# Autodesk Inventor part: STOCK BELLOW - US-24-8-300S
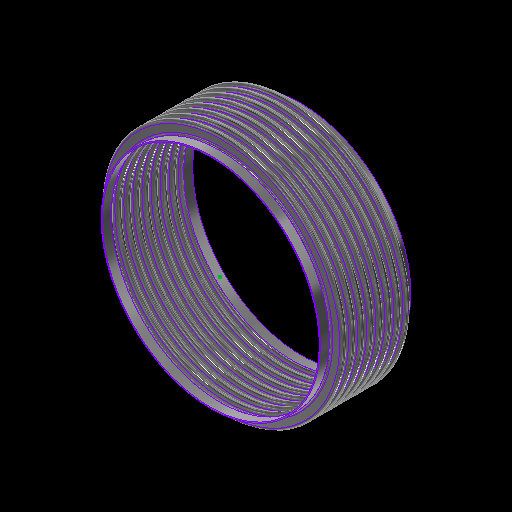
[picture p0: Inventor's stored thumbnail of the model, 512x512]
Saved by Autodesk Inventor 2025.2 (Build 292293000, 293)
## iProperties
Category: 16 GA (0.060 THICK)
RuleStatus: InUse
Created: 2024-01
Part Number: STOCK BELLOW - US-24-8-300S
Project: =STOCK BELLOWS: <Stock Number><SFILL>
Material: ASTM A240-304
Description: =STOCK BELLOWS: <Stock Number>, <SID_> I.D., <SOD_> O.D., <SPLY_> PLY, <Category>, <SNET_CONS> CONS.<PITCH_><STANGENT_> TANGENT<SFILL>
Document SubType Name: Sheet Metal
Designer: GS
Stock Number: U.S-24-8-300S
Surface Area: 27659.1 cm^2
Volume: 4161.61 cm^3
Sheet Metal Rule: Default
Appearance: STAINLESS STEEL
Mass: 33531.3 g
Density: 8.05729 g/cm^3
THK: 0.036
ID: 3.500
OD: 4.250
CONS_: 2
PITCH: 0.500
TANGENT: 0.500
BELLOWS_UPSET: 0.000
d79: 1.000
d82: 1.000
d83: 26.000
d84: 24.000
d174: 8
d214: 8
STHK_: 0.060
SID_: 24.000
SOD_: 26.750
SPITCH_: 1.000
STANGENT__: 1.000
SBELLOWS_UPSET_: 0.000
SDIFF_TAN: 1.000
d252: 2
d275: 2
d287: 0.050
d289: 0.500
d290: 0.000
SOD_NECK: 24 1/4
PLY: 1
PSET: 4.178
PBAR: 1.035
COUNTER: 1.500
NET_TUBE: 3.071
CONS: 2
S_CONS: 0
NET_CONS: 2
ID_M: 88.90 mm
OD_M: 107.95 mm
THK_M: 0.91 mm
ID_U: 3.500 in
OD_U: 4.250 in
THK_U: 0.036 in
TANGENT2: 0.500
TAN_TO_TAN: 1.000 in
d80: 2.571
d81: 10
SID: 2.375
SCONS_: 8
SPITCH: 0.250
STANGENT_: 1.000
SBELLOWS_UPSET: 0.000
SNET_CONS: 8
SS_CONS: 0
SCONS: 8
d190: 8
d191: 1
d192: 1
d193: 8
d194: 0
SIZE: 24.00
PRESSURE: 300
d230: 8
STANGENT: 4.000
SPLY_: 2
d233: 8
d234: 0
d263: 2
d265: 1
d268: 2
d269: 0
d286: 2
d288: 1
d291: 2
d292: 0
SREROLL: 0.750
BLETP: 0.000 ul
PRES_Copy: 85
MATTABLE: 20 GA (0.036 THICK)
PART_NUMBER: U.S-24-8-300S
PITCH_: =, <SPITCH_> PITCH,
CFILL: .
SFILL: .
MESH: ,
COMP: 1.6
EXT: 0.80
LAT: 0.15
ANG: 392
ASR: 10396
LSR: 156893
ANSR: 14604
PRES: 300
COMPM: 16.0
EXTM: 8.0
LATM: 1.50
ASRM: 1820.651
PRESM: 20.684
LSRM: 27476.671
ANSRM: 2557.599
TEMPMIN: 20
TEMPMAX: 800
TEMPMINM: -7
TEMPMAXM: 427
WEIGHTM: 33.531
WEIGHT: 73.924
Author: GS
Keywords: 20 GA (0.036 THICK)
Comments: =STOCK BELLOW - <STOCK NUMBER>
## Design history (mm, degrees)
sketch "Sketch2"
  geometry: L1 (0, -177.245)-(0, 562.856) reference; L2 (45.364, 0)-(44.45, 0); L3 (48.082, -2.718)-(50.343, -2.718); L4 (48.082, -3.632)-(50.343, -3.632); L5 (50.343, -9.982)-(48.082, -9.982); L6 (50.343, -9.068)-(48.082, -9.068); L7 (45.364, -12.7)-(44.45, -12.7); L8 (48.082, 0)-(48.082, -12.7); L9 (50.343, -6.35)-(53.975, -6.35); L10 (44.45, 0)-(44.45, -12.7); L11 (20.376, 102.841)-(20.376, 101.926); L12 (58.262, 457.127)-(58.262, 349.177); L13 (58.262, 444.427)-(58.262, 336.477); L14 (93.133, -58.817)-(93.133, -71.517); L15 (118.746, -66.401)-(118.746, -66.401); L16 (50.343, -9.068)-(50.343, -9.982); L17 (48.082, -9.068)-(48.082, -9.982); L18 (48.082, -9.525)-(50.343, -9.525); L19 (53.975, 0)-(53.975, -12.7); L20 (-50.343, -9.068)-(-50.343, -9.982); L21 (-50.343, -2.718)-(-48.082, -2.718); L22 (-50.343, -3.632)-(-48.082, -3.632); L23 (-48.082, -9.068)-(-50.343, -9.068); L24 (-50.343, -9.525)-(-48.082, -9.525); L25 (-48.082, -9.982)-(-50.343, -9.982); L26 (-48.082, -9.068)-(-48.082, -9.982); L27 (-44.45, 0.653)-(-44.45, -12.047); L28 (-48.082, -6.35)-(-44.45, -6.35); L29 (-50.343, 0.653)-(-50.343, -12.7); L30 (-53.061, 0)-(-53.975, 0); L31 (-53.975, 0)-(-53.975, -12.7); L32 (-53.061, -12.7)-(-53.975, -12.7); A1 r 2.718 centre (48.082, 0) between (45.364, 0) and (48.082, -2.718); A2 r 3.632 centre (48.082, 0) between (44.45, 0) and (48.082, -3.632); A3 r 3.632 centre (50.343, -6.35) between (50.343, -9.982) and (50.343, -2.718); A4 r 2.718 centre (50.343, -6.35) between (50.343, -9.068) and (50.343, -3.632); A5 r 2.718 centre (48.082, -12.7) between (48.082, -9.982) and (45.364, -12.7); A6 r 3.632 centre (48.082, -12.7) between (48.082, -9.068) and (44.45, -12.7); A7 r 3.175 centre (50.343, -6.35) between (50.343, -9.525) and (53.518, -6.35); A8 r 3.175 centre (48.082, -12.7) between (48.082, -9.525) and (44.907, -12.7); A9 r 2.718 centre (-50.343, -12.7) between (-50.343, -9.982) and (-53.061, -12.7); A10 r 2.718 centre (-48.082, -6.35) between (-48.082, -9.068) and (-48.082, -3.632); A11 r 3.175 centre (-48.082, -6.35) between (-48.082, -9.525) and (-44.907, -6.35); A12 r 3.632 centre (-48.082, -6.35) between (-48.082, -9.982) and (-48.082, -2.718); A13 r 3.175 centre (-50.343, -12.7) between (-50.343, -9.525) and (-53.518, -12.7); A14 r 3.632 centre (-50.343, -12.7) between (-50.343, -9.068) and (-53.975, -12.7); A15 r 2.718 centre (-50.343, 0) between (-53.061, 0) and (-50.343, -2.718); A16 r 3.632 centre (-50.343, 0) between (-53.975, 0) and (-50.343, -3.632); 10 further points
  constraints: 62 end point, 38 point on circle, 20 tangent, 16 centre point, 12 parallel, 9 midpoint, 7 vertical, 6 coincident, 6 concentric, 6 point on line, 4 equal radius, 4 perpendicular, 3 horizontal, 1 collinear, 1 horizontal alignment, 10 other
  dimensions: "THK" = 0.9144 distance of L11.start L11.end; "ID" = 88.9 distance of L11.end point (20.376, 13.026); "OD" = 107.95 distance of L12.start L12.end; "PITCH" = 12.7 distance of L12.start L13.start; "TANGENT" = 12.7 distance of L14.start L14.end; "BELLOWS_UPSET" = 0 distance of L15.start L15.end; "d43" = 88.9 diameter of L10 L1 (= ID); "d44" = 107.95 diameter of L9.end L1 (= OD); "d45" = 0.9144 distance between parallel lines of L5 L6 (computed from THK, PLY); "d46" = 3.6322 radius of A3 (computed from PITCH, THK, PLY); "UPSET_PITCH" = 12.7 distance of L2.end L7.end (derived); "SIDEWALL_ANGLE" = 360 deg dimension on L3 L9 (derived); "CON_GAP" = 5.4356 distance of point (48.082, -9.068) point (48.082, -3.632) (derived); "TAN1" = 4.98728 dimension on A8 (derived); "TAN2" = 4.98728 dimension on A7 (derived); "LEG1" = 2.2606 distance of L18.start L18.end (derived); "d278" = 0.9144 distance between parallel lines of L25 L23 (derived); "d279" = 3.6322 radius of A12 (derived); "d280" = 12.7 distance of L30.end L31.end (derived); "d281" = 360 deg dimension on L21 L28 (derived); "d282" = 5.4356 distance of point (-50.343, -9.068) point (-50.343, -3.632) (derived); "d283" = 4.98728 dimension on A13 (derived); "d284" = 4.98728 dimension on A11 (derived); "d285" = 2.2606 distance of L24.start L24.end (derived); "d293" = 88.9 diameter of L27 L1 (derived); "d294" = 107.95 diameter of L31 L1 (derived)
  node "Sketch Rectangular Pattern1" dims "d31" = 25.4, "ID" = 88.9
  node "Sketch Rectangular Pattern2" dims "d39" = 25.4, "PITCH" = 12.7
revolve "CONS" stored, may be unused: angle "d48" = 90 deg
node "BELLOW MIDPLANE"
pattern_linear "Rectangular Pattern2" dims "d52" = 12.7 (= UPSET_PITCH)
sketch "Sketch5"
  geometry: C1 r 45.364 at (0, 0) reference; C2 r 44.45 at (0, 0) reference
extrude "TANGENT" new body sketch "Sketch5" distance "d53" = 12.7 (= TANGENT); taper "d54" = 0 deg
revolve "SAMETAN" stored, may be unused: angle "d65" = 90 deg
revolve "DIFFTAN" stored, may be unused: angle "d70" = 90 deg
sketch "Sketch9"
  geometry: L1 (53.319, 0)-(-53.319, 0) reference; L2 (0, -17.78)-(0, 17.78) reference; L3 (38.085, 0)-(-38.085, 0); L4 (38.085, -11.906)-(38.085, 11.906); L5 (25.385, -11.906)-(25.385, 11.906); L6 (13.15, 11.906)-(13.15, -11.906); L7 (-25.385, -11.906)-(-25.385, 11.906); L8 (-38.085, -11.906)-(-38.085, 11.906); L9 (37.291, -11.906)-(37.291, 11.906); L10 (38.085, -11.906)-(37.291, -11.906); L11 (38.085, 11.906)-(37.291, 11.906); L12 (13.546, 11.906)-(12.753, 11.906); L13 (12.753, 11.906)-(12.753, -11.906); L14 (12.753, -11.906)-(13.546, -11.906); L15 (13.546, -11.906)-(13.546, 11.906); L16 (-13.546, 11.906)-(-13.546, -11.906); L17 (-13.15, 11.906)-(-13.15, -11.906); L18 (-13.546, -11.906)-(-12.753, -11.906); L19 (-12.753, -11.906)-(-12.753, 11.906); L20 (-12.753, 11.906)-(-13.546, 11.906); L21 (-38.085, -11.906)-(-37.291, -11.906); L22 (-37.291, -11.906)-(-37.291, 11.906); L23 (-37.291, 11.906)-(-38.085, 11.906); L24 (-38.085, 11.906)-(-38.085, -11.906); L25 (38.085, -0.397)-(-38.085, -0.397); L26 (-38.085, -0.397)-(-38.085, 0.397); L27 (-38.085, 0.397)-(38.085, 0.397); L28 (38.085, 0.397)-(38.085, -0.397); L29 (-38.085, 11.906)-(38.085, 11.906); L30 (38.085, 11.906)-(38.085, 12.7); L31 (38.085, 12.7)-(-38.085, 12.7); L32 (-38.085, 12.7)-(-38.085, 11.906); L33 (38.085, -11.906)-(-38.085, -11.906); L34 (-38.085, -11.906)-(-38.085, -12.7); L35 (-38.085, -12.7)-(38.085, -12.7); L36 (38.085, -12.7)-(38.085, -11.906); 30 further points
  constraints: 68 end point, 13 midpoint, 13 parallel, 8 horizontal, 7 perpendicular, 6 equal length, 3 point on line, 2 vertical, 14 other
  dimensions: "d115" = 23.8125 distance of L4.start L4.end (derived); "d116" = 12.7 distance between parallel lines of L4 L5 (derived); "d117" = 12.23516 distance between parallel lines of L5 L6 (derived); "d125" = 38.53427 distance between parallel lines of L7 L6 (derived); "d127" = 12.7 distance between parallel lines of L8 L7 (derived); "d128" = 24.93516 distance between parallel lines of L6 L4 (derived); "d130" = 76.16943 distance between parallel lines of L8 L4 (derived); "RULER_THK" = 0.79375 distance between parallel lines of L4 L9; "d135" = 0.79375 distance of L13.end L14.end (derived); "d138" = 26.29911 distance of L13.end L16.end (derived); "d143" = 0.79375 distance of L22.end L8.end (derived); "d144" = 0.79375 distance between parallel lines of L27 L25 (derived)
extrude "RULER" join sketch "Sketch9" distance "d149" = 0.79375 (derived); taper "d150" = 0 deg
extrude "BARS" join sketch "Sketch9" distance "d151" = 0.79375 (derived); taper "d152" = 0 deg
pattern_linear "Rectangular Pattern4" dims "d155" = 26.29911 (derived)
sketch "Sketch13"
  geometry: L1 (93.149, -52.467)-(93.149, -77.867); L2 (307.848, 0)-(304.8, 0); L3 (307.848, -25.4)-(304.8, -25.4); L4 (331.851, -20.574)-(312.674, -20.574); L5 (331.851, -17.526)-(312.674, -17.526); L6 (331.851, -12.7)-(339.725, -12.7); L7 (312.674, -4.826)-(331.851, -4.826); L8 (312.674, 0)-(312.674, -25.4); L9 (304.8, 0)-(304.8, -25.4); L10 (58.254, 183.019)-(58.254, -496.431); L11 (58.254, 157.619)-(58.254, -521.831); L12 (58.254, 106.819)-(58.254, -572.631); L13 (58.254, 81.419)-(58.254, -598.031); L14 (58.254, 56.019)-(58.254, -623.431); L15 (58.254, 30.619)-(58.254, -648.831); L16 (58.254, 5.219)-(58.254, -674.231); L17 (58.254, 132.219)-(58.254, -547.231); L18 (20.376, 103.45)-(20.376, 101.926); L19 (312.674, -7.874)-(331.851, -7.874); L20 (0, -845.681)-(0, 354.469) reference; L21 (-67.945, 0)-(407.67, 0) reference; A1 r 4.826 centre (312.674, 0) between (307.848, 0) and (312.674, -4.826); A2 r 4.826 centre (312.674, -25.4) between (312.674, -20.574) and (307.848, -25.4); A3 r 7.874 centre (312.674, -25.4) between (312.674, -17.526) and (304.8, -25.4); A4 r 4.826 centre (331.851, -12.7) between (331.851, -17.526) and (331.851, -7.874); A5 r 7.874 centre (331.851, -12.7) between (331.851, -20.574) and (331.851, -4.826); A6 r 7.874 centre (312.674, 0) between (304.8, 0) and (312.674, -7.874); 6 further points; 1 other entity
  constraints: 38 end point, 15 point on circle, 9 tangent, 6 centre point, 6 parallel, 5 vertical alignment, 4 point on line, 4 vertical, 3 coincident, 3 concentric, 2 collinear, 2 equal radius, 1 horizontal, 1 perpendicular, 23 other
  dimensions: "SBELLOWS_UPSET_" = 0 distance of point (118.762, -66.401) point (118.762, -66.401); "STOTAL_THK_BELLOW__" = 3.048 distance between parallel lines of L4 L5 (derived); "d224" = 7.874 radius of A5 (derived); "d225" = 25.4 distance of L2.end L3.end (derived); "SSIDEWALL_ANGLE_" = 360 deg dimension on L7 L6 (derived); "SSCON_GAP_" = 9.652 distance of point (312.674, -17.526) point (312.674, -7.874) (derived); "d235" = 609.6 diameter of L9 L20 (derived); "d236" = 679.45 diameter of L6.end L20 (derived)
  node "Sketch Rectangular Pattern4" dims "d228" = 25.4
  node "Sketch Rectangular Pattern5" dims "d229" = 25.4
revolve "SBELLOW" stored, may be unused: angle "d197" = 90 deg
pattern_linear "Rectangular Pattern5" dims "d204" = 25.4 (derived)
revolve "STANGENT" stored, may be unused: angle "d240" = 90 deg
revolve "SSAMETAN" stored, may be unused: angle "d241" = 90 deg
revolve "SDIFFTAN" stored, may be unused: angle "d246" = 90 deg
revolve "INVCON" stored, may be unused: angle "d295" = 90 deg
pattern_linear "Rectangular Pattern6" dims "d298" = 12.7 (derived)
revolve "INVTANGENT" stored, may be unused: angle "d302" = 90 deg
revolve "INVSAMETAN" stored, may be unused: angle "d307" = 90 deg
revolve "INVDIFFTAN" stored, may be unused: angle "d312" = 90 deg
sketch "ID BELLOW MOUNT CALC"
  geometry: L1 (44.45, 0)-(38.1, 0); L2 (38.1, 0)-(38.1, 12.7); L3 (38.1, 12.7)-(44.45, 12.7); L4 (44.45, 12.7)-(44.45, 0); L5 (36.513, 12.7)-(35.598, 12.7); L6 (35.598, 12.7)-(35.598, 0); L7 (35.598, 0)-(36.513, 0); L8 (36.513, 0)-(36.513, 12.7); L9 (0, -2.54)-(0, 15.24) reference; L10 (-8.89, 0)-(53.34, 0) reference; 1 further point
  constraints: 16 end point, 5 parallel, 2 collinear, 2 horizontal, 2 perpendicular
  dimensions: "d314" = 12.7 distance of L5.end L6.end (derived); "d315" = 0.9144 distance of L5.start L5.end (derived); "IG" = 1.5875 distance between parallel lines of L2 L8; "PIPE_OD" = 88.9 diameter of L4 L9; "PIPE_WALL" = 6.35 distance of L2.end L3.end; "ID_MT_BELLOW" = 71.1962 diameter of L6 L9 (derived)
revolve "CFILL" stored, may be unused: angle "d320" = 90 deg
pattern_linear "Rectangular Pattern7" dims "d323" = 12.7 (derived)
revolve "SFILL" stored, may be unused: angle "d324" = 90 deg
pattern_linear "Rectangular Pattern8" dims "d327" = 25.4 (derived)
node "STOCK BELLOW MIDPLANE"
node "BELLOW"
sketch "Sketch6"
  geometry: L1 (-12.7, 45.364)-(0, 45.364); L2 (0, 45.364)-(0, 44.45); L3 (0, 44.45)-(-12.7, 44.45); L4 (-12.7, 44.45)-(-12.7, 45.364); L5 (10.16, 0)-(-60.96, 0) reference; L6 (-38.1, -89.422)-(-38.1, 153.44) reference; 1 further point
  constraints: 8 end point, 2 parallel, 1 horizontal, 1 perpendicular
  dimensions: "d61" = 12.7 distance of L2.end L3.end (derived); "d62" = 0.9144 distance of L1.end L2.end (derived); "d63" = 88.9 diameter of L3 L5 (derived); "d64" = 25.4 distance between parallel lines of L4 L6 (derived)
sketch "Sketch12"
  geometry: 1 further point
sketch "Sketch14"
  geometry: L1 (-25.4, 307.848)-(0, 307.848); L2 (0, 307.848)-(0, 304.8); L3 (0, 304.8)-(-25.4, 304.8); L4 (-25.4, 304.8)-(-25.4, 307.848); L5 (5.08, 0)-(-30.48, 0) reference; L6 (0, -61.57)-(0, 369.418) reference; 1 further point
  constraints: 8 end point, 2 parallel, 1 collinear, 1 horizontal, 1 perpendicular
  dimensions: "d237" = 3.048 distance of L3.end L1.start (derived); "d238" = 609.6 diameter of L3 L5 (derived); "d239" = 25.4 distance of L1.start L1.end (derived); "SOD_NECK" = 615.696 diameter of L1 L5 (derived)
sketch "Sketch15"
  geometry: L1 (-61.57, 0)-(369.418, 0) reference; L2 (304.8, -203.2)-(307.848, -203.2); L3 (307.848, -203.2)-(307.848, -228.6); L4 (307.848, -228.6)-(304.8, -228.6); L5 (304.8, -228.6)-(304.8, -203.2); L6 (0, -276.86)-(0, 60.96) reference; 1 further point
  constraints: 8 end point, 2 parallel, 1 horizontal, 1 perpendicular
  dimensions: "d205" = 25.4 distance of L4.end L2.start (derived); "d206" = 3.048 distance of L3.end L4.end (derived); "d207" = 609.6 diameter of L5 L6 (derived); "d208" = 203.2 distance between parallel lines of L1 L2 (derived)
node "TANGENT_"
node "SAME_TAN"
sketch "Sketch8"
  geometry: L1 (45.364, -25.4)-(44.45, -25.4); L2 (44.45, -25.4)-(44.45, -38.1); L3 (44.45, -38.1)-(45.364, -38.1); L4 (45.364, -38.1)-(45.364, -25.4); L5 (0, -48.26)-(0, 22.86) reference; L6 (-89.422, 0)-(153.44, 0) reference; 1 further point
  constraints: 8 end point, 2 parallel, 1 horizontal, 1 perpendicular
  dimensions: "d66" = 88.9 diameter of L2 L5 (derived); "TOTAL_THK_BELLOW" = 0.9144 distance of L2.end L3.end (derived); "d68" = 25.4 distance between parallel lines of L1 L6 (derived); "d69" = 12.7 distance of L1.end L2.end (derived)
node "DIFF_TAN"
node "Sketch Rectangular Pattern3" dims "d138" = 26.29911 (derived), "d141" = 25.4
node "SBELLOW_"
node "STANGENT_"
node "SSAME_TAN"
sketch "Sketch16"
  geometry: L1 (307.848, -203.2)-(304.8, -203.2); L2 (304.8, -203.2)-(304.8, -228.6); L3 (304.8, -228.6)-(307.848, -228.6); L4 (307.848, -228.6)-(307.848, -203.2); L5 (0, -276.86)-(0, 60.96) reference; L6 (-61.57, 0)-(369.418, 0) reference; 1 further point
  constraints: 8 end point, 2 parallel, 1 horizontal, 1 perpendicular
  dimensions: "SDIFF_TAN" = 25.4 distance of L3.end L1.start; "d243" = 3.048 distance of L2.end L3.end (derived); "d244" = 203.2 distance between parallel lines of L1 L6 (derived); "d245" = 609.6 diameter of L2 L5 (derived)
node "SDIFF_TAN"
body "Solid15"
sketch "Sketch17"
  geometry: L1 (53.975, 12.7)-(53.061, 12.7); L2 (53.061, 12.7)-(53.061, 0); L3 (53.061, 0)-(53.975, 0); L4 (53.975, 0)-(53.975, 12.7); L5 (0, -2.54)-(0, 15.24) reference; L6 (-10.795, 0)-(64.77, 0) reference; 2 further points
  constraints: 8 end point, 2 parallel, 1 horizontal, 1 midpoint, 1 perpendicular, 1 point on line
  dimensions: "INVTANGENT" = 12.7 distance of L3.end L1.start (derived); "d300" = 0.9144 distance of L1.start L1.end (derived); "d301" = 107.95 diameter of L4 L5 (derived)
body "Solid16"
sketch "Sketch18"
  geometry: L1 (53.975, -25.4)-(53.061, -25.4); L2 (53.061, -25.4)-(53.061, -38.1); L3 (53.061, -38.1)-(53.975, -38.1); L4 (53.975, -38.1)-(53.975, -25.4); L5 (-10.795, 0)-(64.77, 0) reference; L6 (0, -48.26)-(0, 22.86) reference; 1 further point
  constraints: 8 end point, 2 parallel, 1 horizontal, 1 perpendicular
  dimensions: "d303" = 25.4 distance between parallel lines of L1 L5 (derived); "d304" = 12.7 distance of L3.end L1.start (derived); "d305" = 0.9144 distance of L2.end L3.end (derived); "d306" = 107.95 diameter of L4 L6 (derived)
body "Solid17"
sketch "Sketch19"
  geometry: L1 (53.975, -25.4)-(53.061, -25.4); L2 (53.061, -25.4)-(53.061, -38.1); L3 (53.061, -38.1)-(53.975, -38.1); L4 (53.975, -38.1)-(53.975, -25.4); L5 (0, -48.26)-(0, 22.86) reference; L6 (-10.795, 0)-(64.77, 0) reference; 1 further point
  constraints: 8 end point, 2 parallel, 1 horizontal, 1 perpendicular
  dimensions: "d308" = 12.7 distance of L1.end L2.end (derived); "d309" = 107.95 diameter of L4 L5 (derived); "d310" = 0.9144 distance of L2.end L3.end (derived); "d311" = 25.4 distance between parallel lines of L1 L6 (derived)
body "Solid18"
body "Solid19"
body "Solid20"
other parameters: "BMPL" = -101.6, "PSET" = 106.1212 (computed from OD, THK, PLY) [user parameter], "PBAR" = 26.29911 (= 0.570796 x PITCH + OD - ID) [user parameter; used in 1 equation term], "COUNTER" = 15 [user parameter], "NET_TUBE" = 77.99823 (computed from CONS_, PBAR, TANGENT) [user parameter], "S_CONS" = 0 [user parameter; used in 1 equation term], "ID_M" = 88.9 (= ID) [user parameter], "OD_M" = 107.95 (= OD) [user parameter], "THK_M" = 0.9144 (= THK) [user parameter], "ID_U" = 88.9 (= ID) [user parameter], "OD_U" = 107.95 (= OD) [user parameter], "THK_U" = 0.9144 (= THK) [user parameter], "D_UNITS" = 0 [user parameter], "TANGENT2" = 12.7 [user parameter], "TAN_TO_TAN" = 25.4 [user parameter], "OD_NECK" = 90.7288 [user parameter], "d79" = 25.4, "d80" = 65.29823 [user parameter], "d82" = 25.4, "d83" = 660.4, "d84" = 609.6, "sa_0" = 4, "FRAME_THK" = 0.79375 [user parameter], "CON_FLAT" = 12.23516 [user parameter], "SID" = 60.325 [user parameter], "SPITCH" = 6.35 [user parameter], "STANGENT_" = 25.4 [user parameter], "SBELLOWS_UPSET" = 0 [user parameter], "SS_CONS" = 0 [user parameter], "STAN_TO_TAN_" = 203.2 [user parameter], "d100" = 3.048 [user parameter], "d191" = 25.4 [user parameter], "d194" = 0 [user parameter], "STANGENT" = 101.6 [user parameter], "d234" = 0 [user parameter], "SUPSET_PITCH_" = 25.4 [user parameter], "d269" = 0 [user parameter], "d287" = 1.27, "d289" = 12.7, "d290" = 0, "d292" = 0 [user parameter], "Thickness" = 3.048 (derived), "KFactor" = 4.4, "BendRadius" = 3.048 (derived), "BendReliefWidth" = 3.048 (derived), "BendReliefDepth" = 1.524 (derived), "CornerReliefSize" = 12.192 (derived), "SeamGap" = 0.00508, "MinimumRemnant" = 6.096 (derived), "TransitionRadius" = 3.048 (derived), "JacobiRadiusSize" = 3.048 (derived), "GapSize" = 3.048 (derived), "SREROLL" = 19.05 [user parameter], "CUR_STK_PITCH" = 25.4 [user parameter], "d328" = -101.6 (derived), "ASR" = 103960 [user parameter], "LSR" = 1568930 [user parameter], "ANSR" = 146040 [user parameter], "BLETP" = 0 [user parameter], "ASRM" = 18206.5148 [user parameter], "PRESM" = 206.83949 [user parameter], "LSRM" = 274766.7109 [user parameter], "ANSRM" = 25575.9852 [user parameter], "TEMPMIN" = 2664.83333 [user parameter], "TEMPMAX" = 6998.16667 [user parameter], "TEMPMINM" = 2664.83333 [user parameter], "TEMPMAXM" = 6998.16667 [user parameter], "WEIGHT" = 335.31273 [user parameter], "WEIGHTM" = 0.33531 [user parameter]
